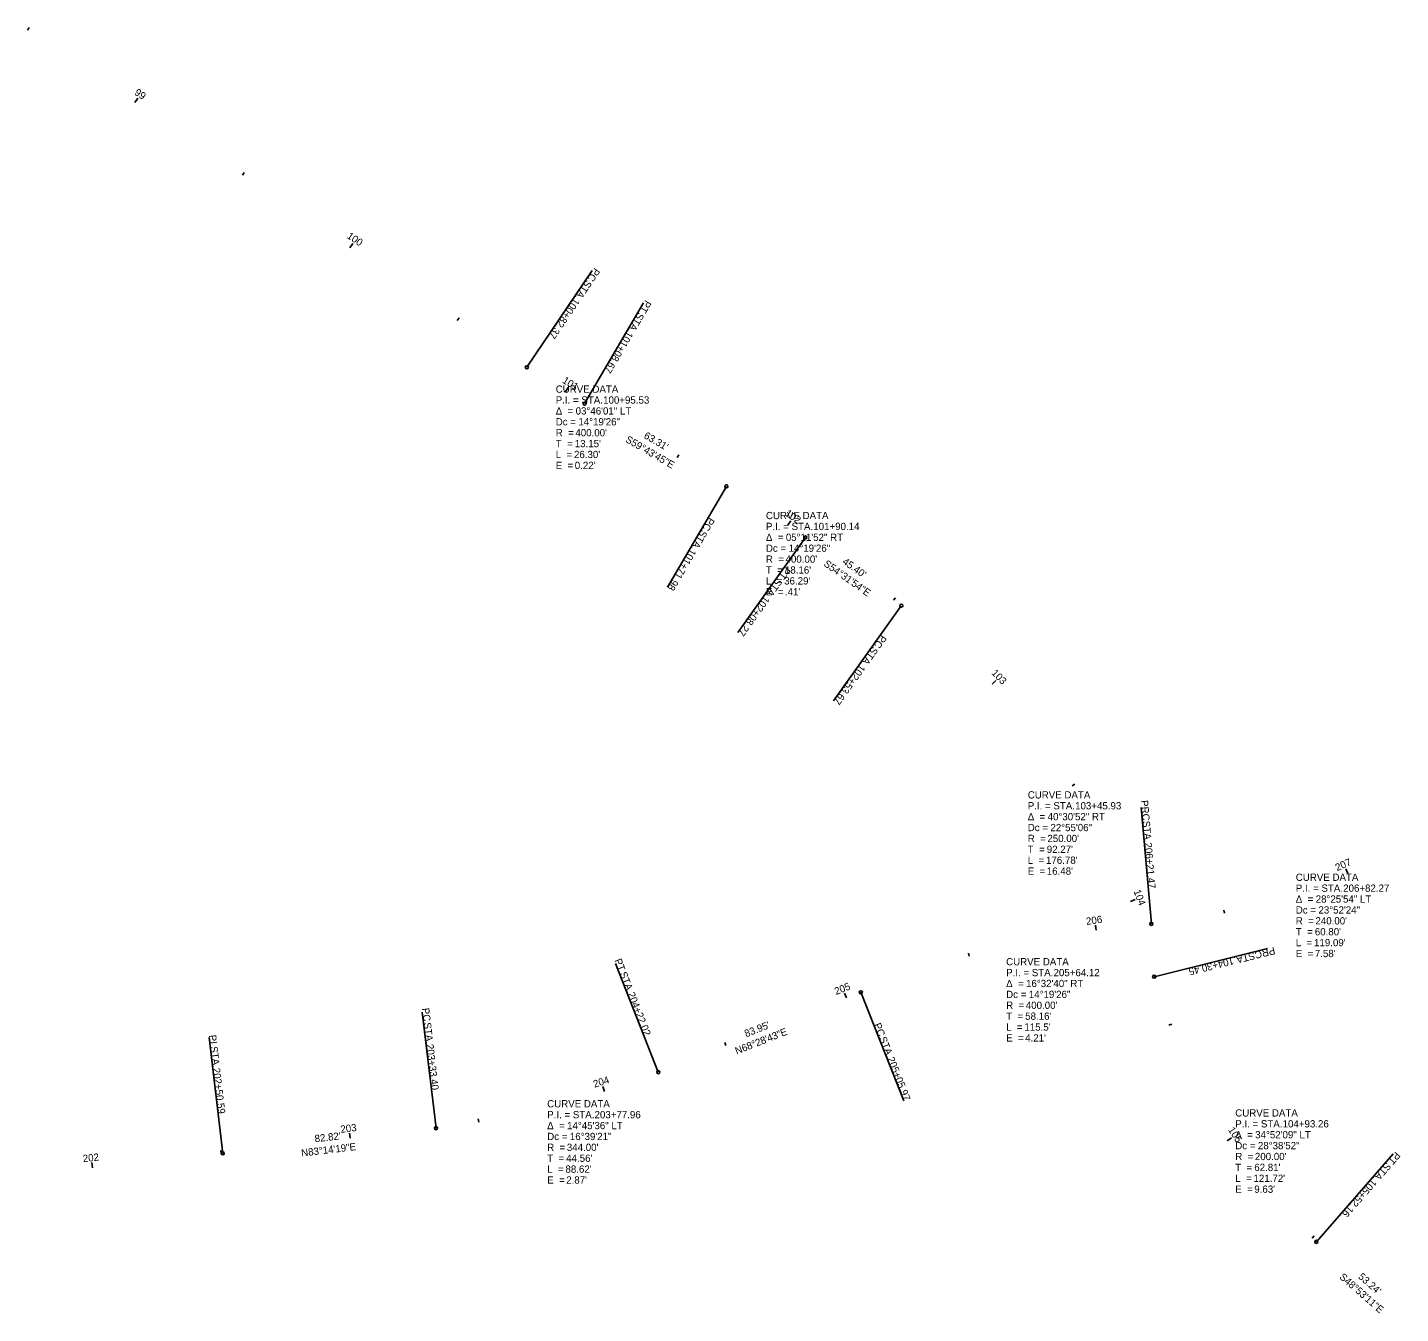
# Model space of a CAD drawing. Extents: x 1600023 to 1602131, y 285824 to 287284.
# Drawn here: x 1600580 to 1601109, y 286542 to 287038 of the extents above; entities that cross this region are included whole.
import ezdxf

# ---------------------------------------------------------------- set-up
doc = ezdxf.new("R2010")
doc.units = 0
for name, color, linetype in [('PM_P_CL_Double_Solid', 7, 'Continuous'), ('PM_P_Dotted_Line', 7, 'Continuous'), ('PM_P_Edge_Line', 7, 'Continuous'), ('PM_P_Transverse_Line', 7, 'Continuous'), ('PM_P_Yield_Line', 7, 'Continuous')]:
    doc.layers.add(name, color=color, linetype=linetype)

msp = doc.modelspace()

# ---------------------------------------------------------------- linework, layer by layer
at = {"layer": 'PM_P_CL_Double_Solid'}
for p, q in [((1600772.53, 286906.56), (1600797.72, 286943.85)), ((1600794.79, 286892.56), (1600817.48, 286931.43)), ((1600849.47, 286860.65), (1600826.79, 286821.79)), ((1600879.94, 286840.96), (1600853.82, 286804.31)), ((1600916.91, 286814.62), (1600890.8, 286777.97)), ((1601013.35, 286691.95), (1601009.45, 286736.78)), ((1601014.4, 286671.56), (1601058.06, 286682.46)), ((1600823.21, 286634.77), (1600806.71, 286676.63)), ((1600901.31, 286665.57), (1600917.82, 286623.7)), ((1600737.52, 286613.18), (1600732.22, 286657.87)), ((1600655.28, 286603.43), (1600649.98, 286648.12)), ((1601076.94, 286569.32), (1601106.53, 286603.23))]:
    msp.add_line(p, q, dxfattribs=at)
for centre in [(1600772.53, 286906.56), (1600794.79, 286892.56), (1600849.47, 286860.65), (1600879.94, 286840.96), (1600916.91, 286814.62), (1601013.35, 286691.95), (1601014.4, 286671.56), (1600901.31, 286665.57), (1600823.21, 286634.77), (1600737.52, 286613.18), (1600655.28, 286603.43), (1601076.94, 286569.32)]:
    msp.add_circle(centre, 0.6, dxfattribs=at)
at = {"layer": 'PM_P_Transverse_Line'}
for p, q in [((1600579.97, 287036.63), (1600580.64, 287037.62)), ((1600621.4, 287008.64), (1600622.52, 287010.3)), ((1600662.84, 286980.65), (1600663.51, 286981.65)), ((1600704.27, 286952.66), (1600705.39, 286954.32)), ((1600745.7, 286924.68), (1600746.38, 286925.67)), ((1600787.35, 286897.02), (1600788.4, 286898.72)), ((1600830.49, 286871.73), (1600831.09, 286872.77)), ((1600873.15, 286845.69), (1600874.28, 286847.34)), ((1600913.92, 286816.75), (1600914.62, 286817.73)), ((1600951.95, 286784.4), (1600953.39, 286785.79)), ((1600982.8, 286745.17), (1600983.82, 286745.81)), ((1601089.09, 286711.32), (1601088.28, 286713.15)), ((1601005.25, 286700.58), (1601007.12, 286701.3)), ((1601041.56, 286696.1), (1601041.31, 286697.28)), ((1600992.02, 286689.51), (1600991.74, 286691.49)), ((1600943.08, 286679.43), (1600942.76, 286680.59)), ((1600895.76, 286663.38), (1600895.03, 286665.24)), ((1601020.06, 286652.85), (1601021.19, 286653.26)), ((1600849.25, 286645.03), (1600848.8, 286646.15)), ((1600802.49, 286627.35), (1600801.87, 286629.26)), ((1600753.95, 286615.53), (1600753.75, 286616.71)), ((1600704.35, 286609.25), (1600704.12, 286611.23)), ((1601042.53, 286608.33), (1601044.19, 286609.45)), ((1600654.7, 286603.36), (1600654.57, 286604.56)), ((1600605, 286597.91), (1600604.78, 286599.89)), ((1601075.32, 286570.76), (1601076.12, 286571.65))]:
    msp.add_line(p, q, dxfattribs=at)

# ---------------------------------------------------------------- texts
at = {"layer": 'PM_P_CL_Double_Solid'}
for s, rotation, p in [(' STA. ', 235.9623, (1600796.06, 286941.32)), ('PC', 235.9623, (1600798.63, 286945.12)), ('100+82.37', 235.9623, (1600790.77, 286933.49)), ('PT', 239.7293, (1600818.26, 286932.68)), (' STA. ', 239.7293, (1600816.03, 286928.87)), ('101+08.67', 239.7293, (1600811.27, 286920.71)), ('PC', 239.7293, (1600842.69, 286848.95)), (' STA. ', 239.7293, (1600840.38, 286844.99)), ('101+71.98', 239.7293, (1600835.61, 286836.83)), ('PT', 234.5316, (1600872.12, 286829.92)), (' STA. ', 234.5316, (1600869.56, 286826.33)), ('102+08.27', 234.5316, (1600864.08, 286818.63)), ('PC', 234.5316, (1600909.15, 286803.65)), (' STA. ', 234.5316, (1600906.49, 286799.92)), ('102+53.67', 234.5316, (1600901, 286792.22)), ('PRC', 274.977, (1601009.25, 286739.51)), (' STA. ', 274.977, (1601009.85, 286732.59)), ('206+21.47', 274.977, (1601010.67, 286723.18)), (' STA. ', 194.0171, (1601053.89, 286681.38)), ('PRC', 194.0171, (1601060.62, 286683.06)), ('PT', 291.5214, (1600806.25, 286677.89)), ('104+30.45', 194.0171, (1601044.72, 286679.09)), (' STA. ', 291.5214, (1600807.87, 286673.79)), ('204+22.02', 291.5214, (1600811.34, 286664.99)), ('PC', 276.7614, (1600732.09, 286659.35)), ('PI', 276.7614, (1600649.92, 286648.98)), (' STA. ', 276.7614, (1600732.63, 286654.8)), ('PC', 291.5214, (1600906.28, 286653.08)), (' STA. ', 276.7614, (1600650.32, 286645.61)), ('203+33.40', 276.7614, (1600733.74, 286645.41)), (' STA. ', 291.5214, (1600907.96, 286648.81)), ('205+05.97', 291.5214, (1600911.43, 286640.02)), ('202+50.59', 276.7614, (1600651.43, 286636.23)), ('PT', 228.8864, (1601107.49, 286604.27)), (' STA. ', 228.8864, (1601104.59, 286600.94)), ('105+52.16', 228.8864, (1601098.37, 286593.82))]:
    msp.add_text(s, height=2.8, rotation=rotation, dxfattribs=at).set_placement(p)
at = {"layer": 'PM_P_Dotted_Line'}
for s, rotation, p in [("63.31'", 329.7293, (1600817.35, 286879.45)), ("45.40'", 324.5316, (1600893.92, 286831.05)), ("83.95'", 21.5214, (1600857.07, 286648.17)), ("82.82'", 6.7614, (1600690.87, 286607.69)), ("53.24'", 318.8864, (1601092.83, 286555.51))]:
    msp.add_text(s, height=2.8, rotation=rotation, dxfattribs=at).set_placement(p)
at = {"layer": 'PM_P_Edge_Line'}
for s, rotation, p in [('S59°43\'45"E', 329.7293, (1600810.26, 286877.98)), ('S54°31\'54"E', 324.5316, (1600886.73, 286830.23)), ('N68°28\'43"E', 21.5214, (1600853.45, 286641.53)), ('N83°14\'19"E', 6.7614, (1600685.68, 286602.2)), ('S48°53\'11"E', 318.8864, (1601085.6, 286555.4))]:
    msp.add_text(s, height=2.8, rotation=rotation, dxfattribs=at).set_placement(p)
at = {"layer": 'PM_P_Transverse_Line'}
for s, rotation, p in [('99', 325.9623, (1600620.98, 287011.94)), ('100', 325.9623, (1600702.9, 286956.61)), ('101', 328.4871, (1600785.97, 286900.79)), ('102', 325.7158, (1600871.85, 286849.6)), ('103', 313.9131, (1600951.48, 286788.49)), ('207', 23.7245, (1601084.96, 286712.24)), ('104', 290.9948, (1601006.41, 286704.53)), ('206', 8.0525, (1600988.34, 286691.52)), ('205', 21.5214, (1600891.77, 286664.49)), ('204', 17.854, (1600798.61, 286628.73)), ('203', 6.7614, (1600700.81, 286611.34)), ('105', 303.9428, (1601042.76, 286612.47)), ('202', 6.2675, (1600601.46, 286600.03))]:
    msp.add_text(s, height=2.8, rotation=rotation, dxfattribs=at).set_placement(p)
at = {"layer": 'PM_P_Yield_Line'}
for s, p in [('CURVE DATA', (1600783.66, 286896.76)), ('P.I. = STA. ', (1600783.66, 286892.56)), ('100+95.53', (1600801.93, 286892.56)), ('Δ  = ', (1600783.66, 286888.36)), ('03°46\'01" LT', (1600791.34, 286888.36)), ('Dc = ', (1600783.66, 286884.16)), ('R  = ', (1600783.66, 286879.96)), ("400.00'", (1600791.24, 286879.96)), ('14°19\'26"', (1600792.4, 286884.16)), ('T  = ', (1600783.66, 286875.76)), ("13.15'", (1600791, 286875.76)), ('L  = ', (1600783.66, 286871.56)), ("26.30'", (1600790.7, 286871.56)), ('E  = ', (1600783.66, 286867.36)), ("0.22'", (1600791, 286867.36)), ('CURVE DATA', (1600864.7, 286848.01)), ('P.I. = STA. ', (1600864.7, 286843.81)), ('101+90.14', (1600882.97, 286843.81)), ('Δ  = ', (1600864.7, 286839.61)), ('05°11\'52" RT', (1600872.38, 286839.61)), ('Dc = ', (1600864.7, 286835.41)), ('14°19\'26"', (1600873.44, 286835.41)), ('T  = ', (1600864.7, 286827.01)), ('R  = ', (1600864.7, 286831.21)), ("18.16'", (1600872.04, 286827.01)), ("400.00'", (1600872.28, 286831.21)), ('L  = ', (1600864.7, 286822.81)), ("36.29'", (1600871.74, 286822.81)), ('E  = ', (1600864.7, 286818.61)), (".41'", (1600872.04, 286818.61)), ('CURVE DATA', (1600965.66, 286740.29)), ('P.I. = STA. ', (1600965.66, 286736.09)), ('103+45.93', (1600983.93, 286736.09)), ('Δ  = ', (1600965.66, 286731.89)), ('40°30\'52" RT', (1600973.34, 286731.89)), ('Dc = ', (1600965.66, 286727.69)), ('22°55\'06"', (1600974.4, 286727.69)), ('R  = ', (1600965.66, 286723.49)), ("250.00'", (1600973.24, 286723.49)), ('T  = ', (1600965.66, 286719.29)), ('L  = ', (1600965.66, 286715.09)), ("176.78'", (1600972.7, 286715.09)), ("92.27'", (1600973, 286719.29)), ('E  = ', (1600965.66, 286710.89)), ("16.48'", (1600973, 286710.89)), ('CURVE DATA', (1601069.01, 286708.52)), ('P.I. = STA. ', (1601069.01, 286704.32)), ('206+82.27', (1601087.28, 286704.32)), ('Δ  = ', (1601069.01, 286700.12)), ('28°25\'54" LT', (1601076.69, 286700.12)), ('Dc = ', (1601069.01, 286695.92)), ('23°52\'24"', (1601077.75, 286695.92)), ('R  = ', (1601069.01, 286691.72)), ("240.00'", (1601076.59, 286691.72)), ('T  = ', (1601069.01, 286687.52)), ('L  = ', (1601069.01, 286683.32)), ("119.09'", (1601076.05, 286683.32)), ("60.80'", (1601076.35, 286687.52)), ('E  = ', (1601069.01, 286679.12)), ("7.58'", (1601076.35, 286679.12)), ('CURVE DATA', (1600957.33, 286675.96)), ('Δ  = ', (1600957.33, 286667.56)), ('P.I. = STA. ', (1600957.33, 286671.76)), ('16°32\'40" RT', (1600965.01, 286667.56)), ('205+64.12', (1600975.6, 286671.76)), ('Dc = ', (1600957.33, 286663.36)), ('14°19\'26"', (1600966.07, 286663.36)), ('R  = ', (1600957.33, 286659.16)), ("400.00'", (1600964.91, 286659.16)), ('T  = ', (1600957.33, 286654.96)), ("58.16'", (1600964.67, 286654.96)), ('L  = ', (1600957.33, 286650.76)), ('E  = ', (1600957.33, 286646.56)), ("115.5'", (1600964.37, 286650.76)), ("4.21'", (1600964.67, 286646.56)), ('CURVE DATA', (1600780.37, 286621.17)), ('P.I. = STA. ', (1600780.37, 286616.97)), ('203+77.96', (1600798.63, 286616.97)), ('CURVE DATA', (1601045.67, 286617.64)), ('Δ  = ', (1600780.37, 286612.77)), ('14°45\'36" LT', (1600788.04, 286612.77)), ('Δ  = ', (1601045.67, 286609.24)), ('P.I. = STA. ', (1601045.67, 286613.44)), ('34°52\'09" LT', (1601053.35, 286609.24)), ('104+93.26', (1601063.94, 286613.44)), ('Dc = ', (1600780.37, 286608.57)), ('R  = ', (1600780.37, 286604.37)), ("344.00'", (1600787.95, 286604.37)), ('16°39\'21"', (1600789.11, 286608.57)), ('Dc = ', (1601045.67, 286605.04)), ('28°38\'52"', (1601054.41, 286605.04)), ('T  = ', (1600780.37, 286600.17)), ("44.56'", (1600787.7, 286600.17)), ('R  = ', (1601045.67, 286600.84)), ("200.00'", (1601053.25, 286600.84)), ('L  = ', (1600780.37, 286595.97)), ("88.62'", (1600787.41, 286595.97)), ('T  = ', (1601045.67, 286596.64)), ("62.81'", (1601053.01, 286596.64)), ('E  = ', (1600780.37, 286591.77)), ("2.87'", (1600787.71, 286591.77)), ('L  = ', (1601045.67, 286592.44)), ('E  = ', (1601045.67, 286588.24)), ("121.72'", (1601052.71, 286592.44)), ("9.63'", (1601053.01, 286588.24))]:
    msp.add_text(s, height=2.8, dxfattribs=at).set_placement(p)

doc.saveas('drawing.dxf')
